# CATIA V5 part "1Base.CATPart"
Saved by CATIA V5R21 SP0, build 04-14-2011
Part number: Base
Bounding box of the stored display mesh (mm): x -49.234 to 49.234, y -29.276 to 56, z -1.5 to 10
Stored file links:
  F:\教程\Robotic_Arm_Arduino_Kinect\机械臂CAD\Arm_Detailed_Design_Assembly\Base_Bear_assem_base.CATPart
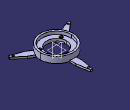
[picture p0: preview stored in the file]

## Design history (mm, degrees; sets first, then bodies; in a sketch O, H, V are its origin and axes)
Body1 (main body)
  Sketch1 on xy-plane, origin (0, 0, 0), H (1, 0, 0), V (0, 1, 0)
    circle A1 centre (0, 0) radius 26.5
    radius A1 = 26.5
  Pad1: profile Sketch1, direction (0, 0, 1), length 10
  Sketch2 on end face of Pad1, origin (0, 0, 10), H (1, 0, 0), V (0, 1, 0)
    circle A1 centre (0, 0) radius 23.5
    radius A1 = 23.5
  Pocket1: profile Sketch2, direction (0, 0, -1), up to start face of Pad1, offset -5
  Sketch3 on end face of Pocket1, origin (0, 0, 5), H (1, 0, 0), V (0, 1, 0)
    circle A1 centre (0, 0) radius 16
    radius A1 = 16
  Pocket2: profile Sketch3, direction (0, 0, -1), through (limit type 3)
  Sketch4 on end face of Pocket1, origin (0, 0, 5), H (1, 0, 0), V (0, 1, 0)
    circle A1 centre (0, 19.5) radius 2.5
    point P1 (0, 19.5)
    circle A2 centre (-16.8875, -9.75) radius 2.5
    circle A3 centre (16.8875, -9.75) radius 2.5
    radius A1 = 2.5
    distance P1 H = 19.5
    coincidence: P1 V
  Pocket3: profile Sketch4, direction (0, 0, -1), length 1.5
  Sketch5 on end face of Pocket3, origin (0, 0, 3.5), H (1, 0, 0), V (0, 1, 0)
    circle A1 centre (0, 19.5) radius 1.5
    point P1 (0, 19.5)
    circle A2 centre (-16.8875, -9.75) radius 1.5
    circle A3 centre (16.8875, -9.75) radius 1.5
    radius A1 = 1.5
    distance P1 H = 19.5
    coincidence: P1 V
  Pocket4: profile Sketch5, direction (0, 0, -1), through (limit type 3)
  Sketch6 on start face of Pad1, origin (0, 0, 0), H (1, 0, 0), V (0, -1, 0)
    line L1 (-5, -13.8154) -> (5, -13.8154)
    line L2 (5, -13.8154) -> (5, -28.4504)
    line L3 (5, -28.4504) -> (-5, -28.4504)
    line L4 (-5, -28.4504) -> (-5, -13.8154)
    line L5 (22.1387, 18.5553) -> (27.1387, 9.8951)
    line L6 (9.4645, 11.2378) -> (22.1387, 18.5553)
    line L7 (27.1387, 9.8951) -> (14.4645, 2.5776)
    line L8 (14.4645, 2.5776) -> (9.4645, 11.2378)
    line L9 (-27.1387, 9.8951) -> (-22.1387, 18.5553)
    line L10 (-14.4645, 2.5776) -> (-27.1387, 9.8951)
    line L11 (-22.1387, 18.5553) -> (-9.4645, 11.2378)
    line L12 (-9.4645, 11.2378) -> (-14.4645, 2.5776)
    distance L2 V = 5
    distance V L4 = 5
    horizontal: L1 H, L3 H
    vertical: L2 V, L4 V
  Pocket5: profile Sketch6, direction (0, 0, 1), length 1.5
Body2
  Sketch7 on end face of Pocket5, origin (0, 0, 1.5), H (1, 0, 0), V (0, -1, 0)
    line L1 (-5, -16) -> (5, -16)
    line L2 (5, -16) -> (5, -36)
    point P2 (5, -36)
    line L3 (5, -36) -> (1.4735, -56)
    line L4 (1.4735, -56) -> (-1.4735, -56)
    line L5 (-1.4735, -56) -> (-5, -36)
    point P5 (-5, -36)
    line L6 (-5, -36) -> (-5, -16)
    reference projected line E1 (-5, -13.8154) -> (-5, -28.4504) from edge [end face of Pocket5 | face of Pocket5 from Sketch6.L4]
    reference projected line E2 (5, -28.4504) -> (5, -13.8154) from edge [end face of Pocket5 | face of Pocket5 from Sketch6.L2]
    reference projected arc E3 centre (0, 0) radius 16 from (-10.6624, 11.9295) to (-15.6624, 3.2692) ccw from edge [end face of Pocket5 | face of Pocket2 from Sketch3.A1]
    circle A1 centre (0, -51) radius 1.5
    point P7 (0, -51)
    circle A2 centre (0, -19.5) radius 1.5
    point P8 (0, -19.5)
    reference projected circle E6 centre (0, -19.5) radius 1.5 from edge [end face of Pocket5 | face of Pocket4 from Sketch5.A1]
    angle L5 L6 = 170
    angle L3 L2 = 170
    distance L1 L4 = 40
    distance P2 L1 = 20
    distance P5 L1 = 20
    radius A1 = 1.5
    distance P7 L4 = 5
    horizontal: L1 H, L4 H
    vertical: L2 V, L6 V
    coincidence: L6 E1, L2 E2, P7 V, P8 V, A2 E6
    tangency: L1 E3
  Pad2: profile Sketch7, direction (0, 0, -1), length 3
  CircPattern1: of Pad2, instances 3, angular step 120, axis from Z axis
